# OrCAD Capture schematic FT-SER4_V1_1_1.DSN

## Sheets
1 INDEX: title: INDEX; rev: 1.1; note: 17 HaYetsira Street; note: Yokneam Illit, Israel 2069208
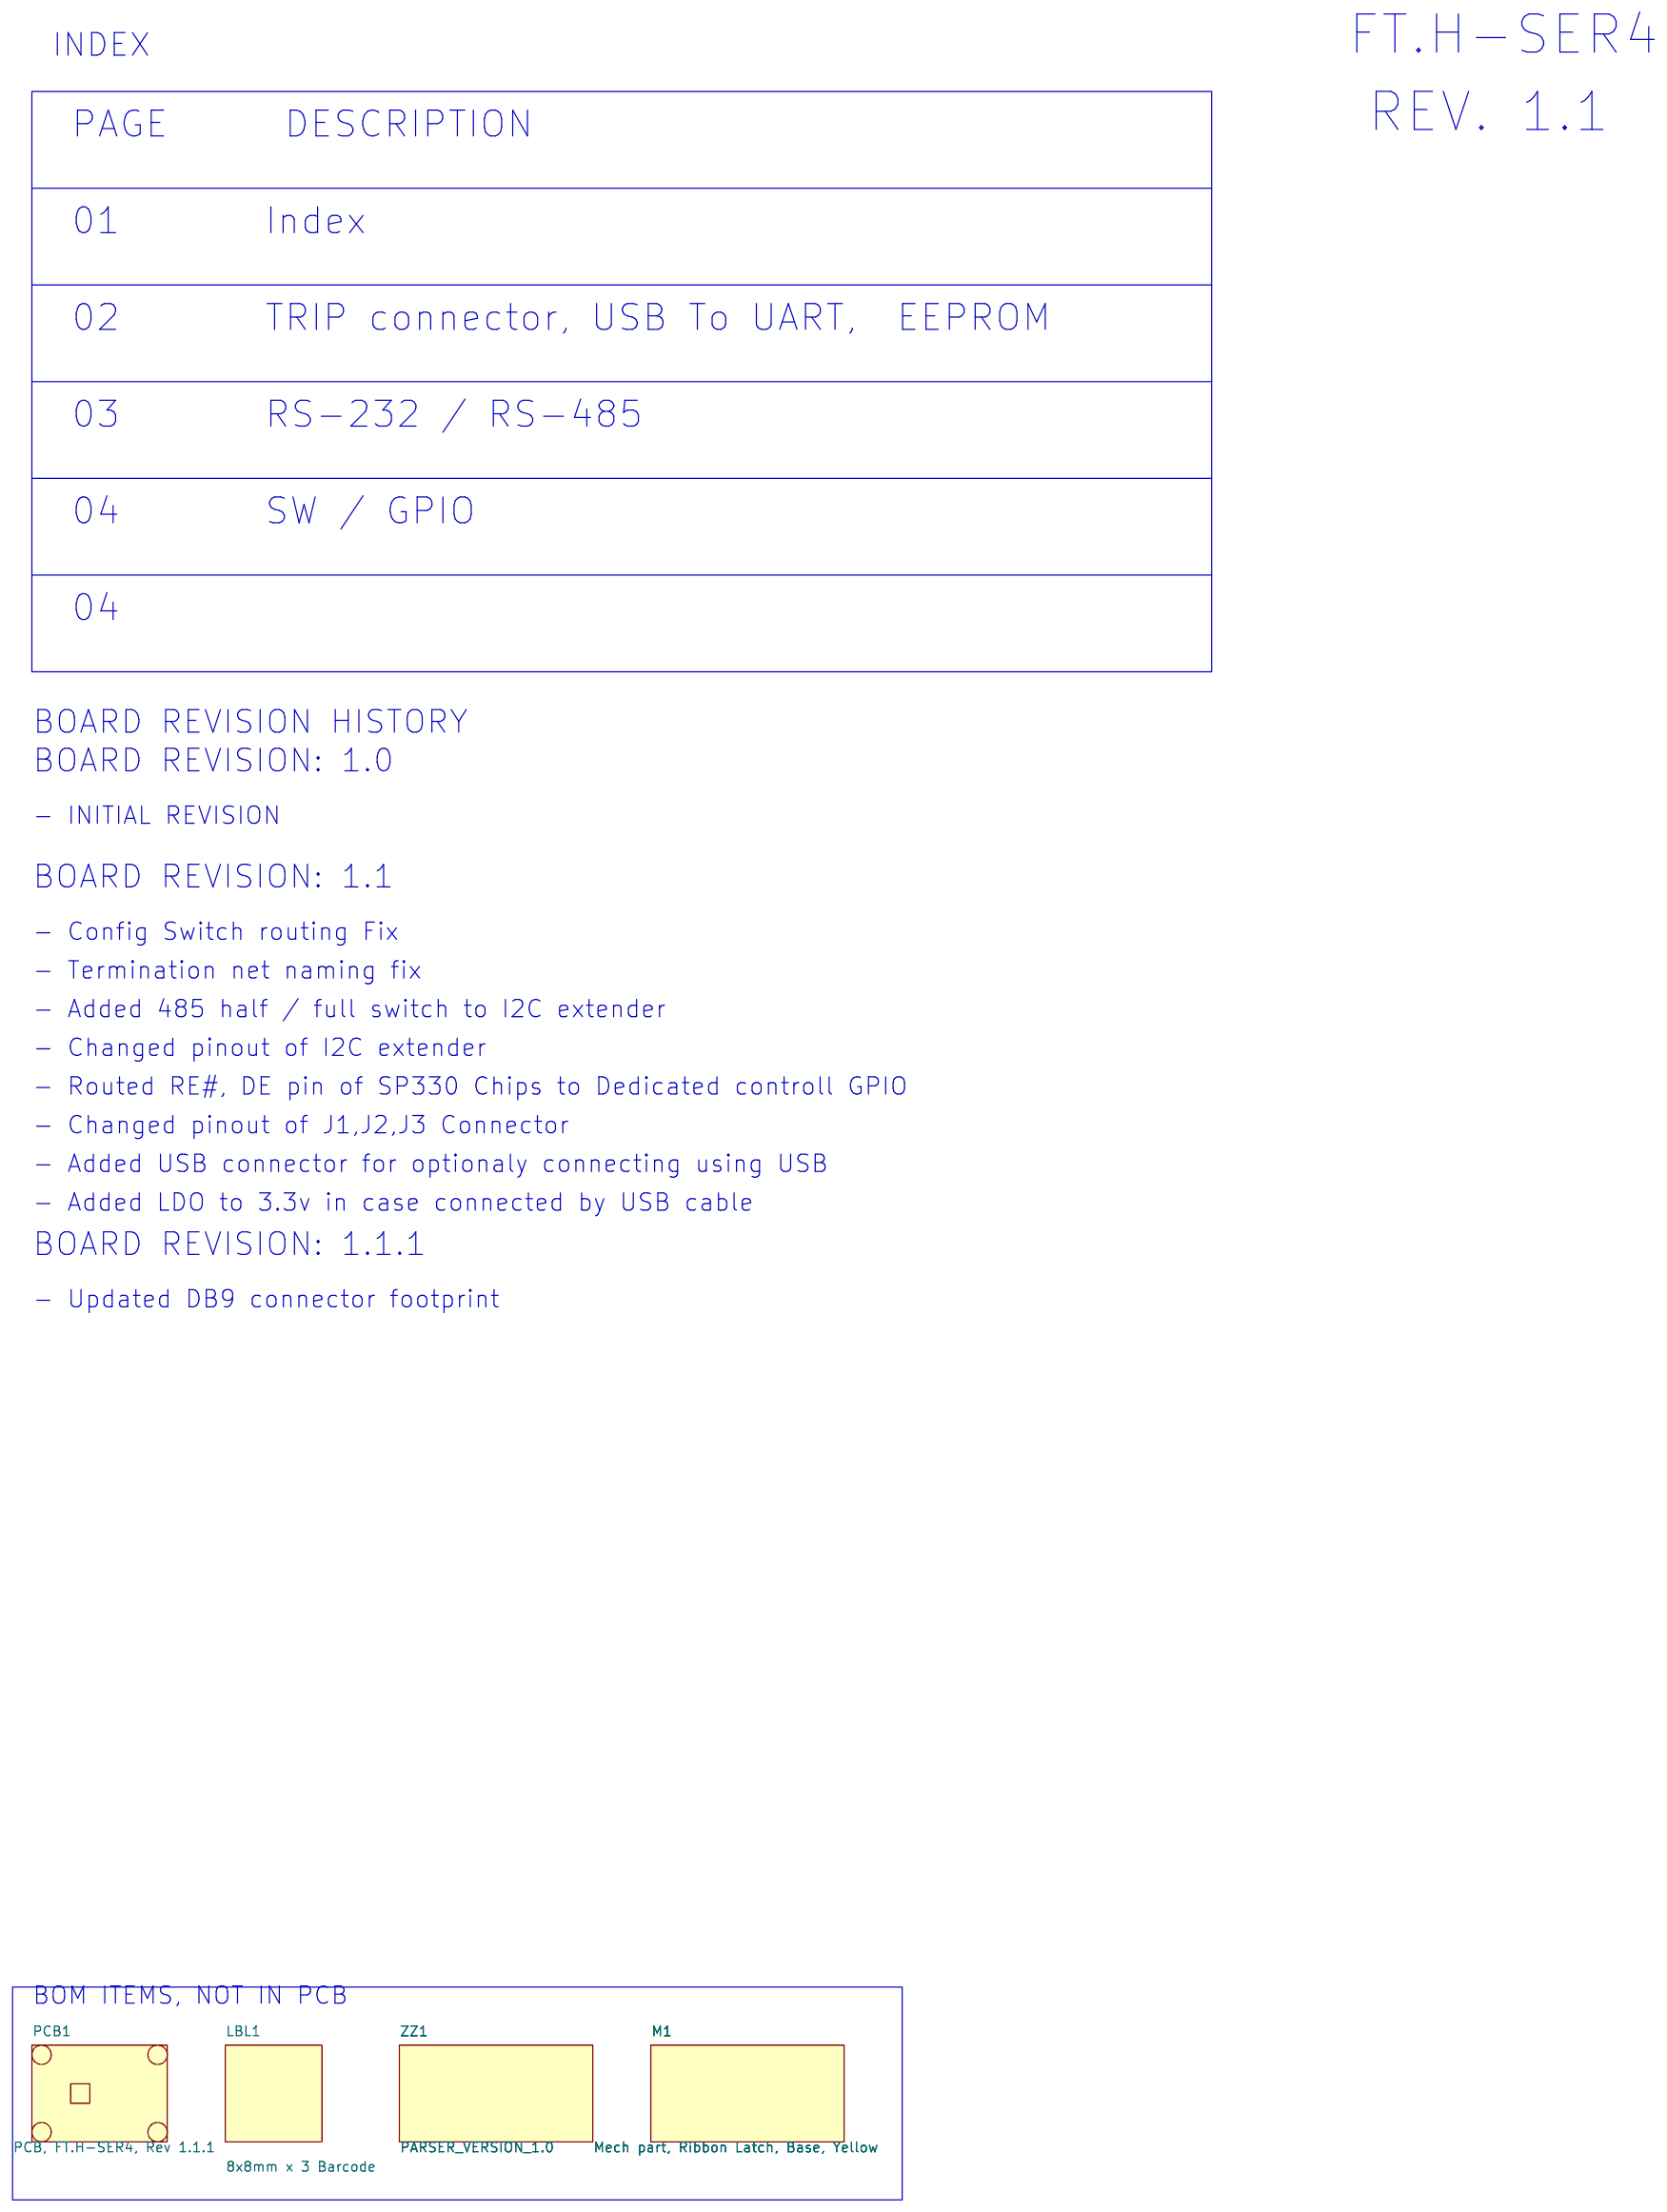
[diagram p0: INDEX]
2 TRIP + USB2UART: size A3; title: 02-TRIP + USB2UART
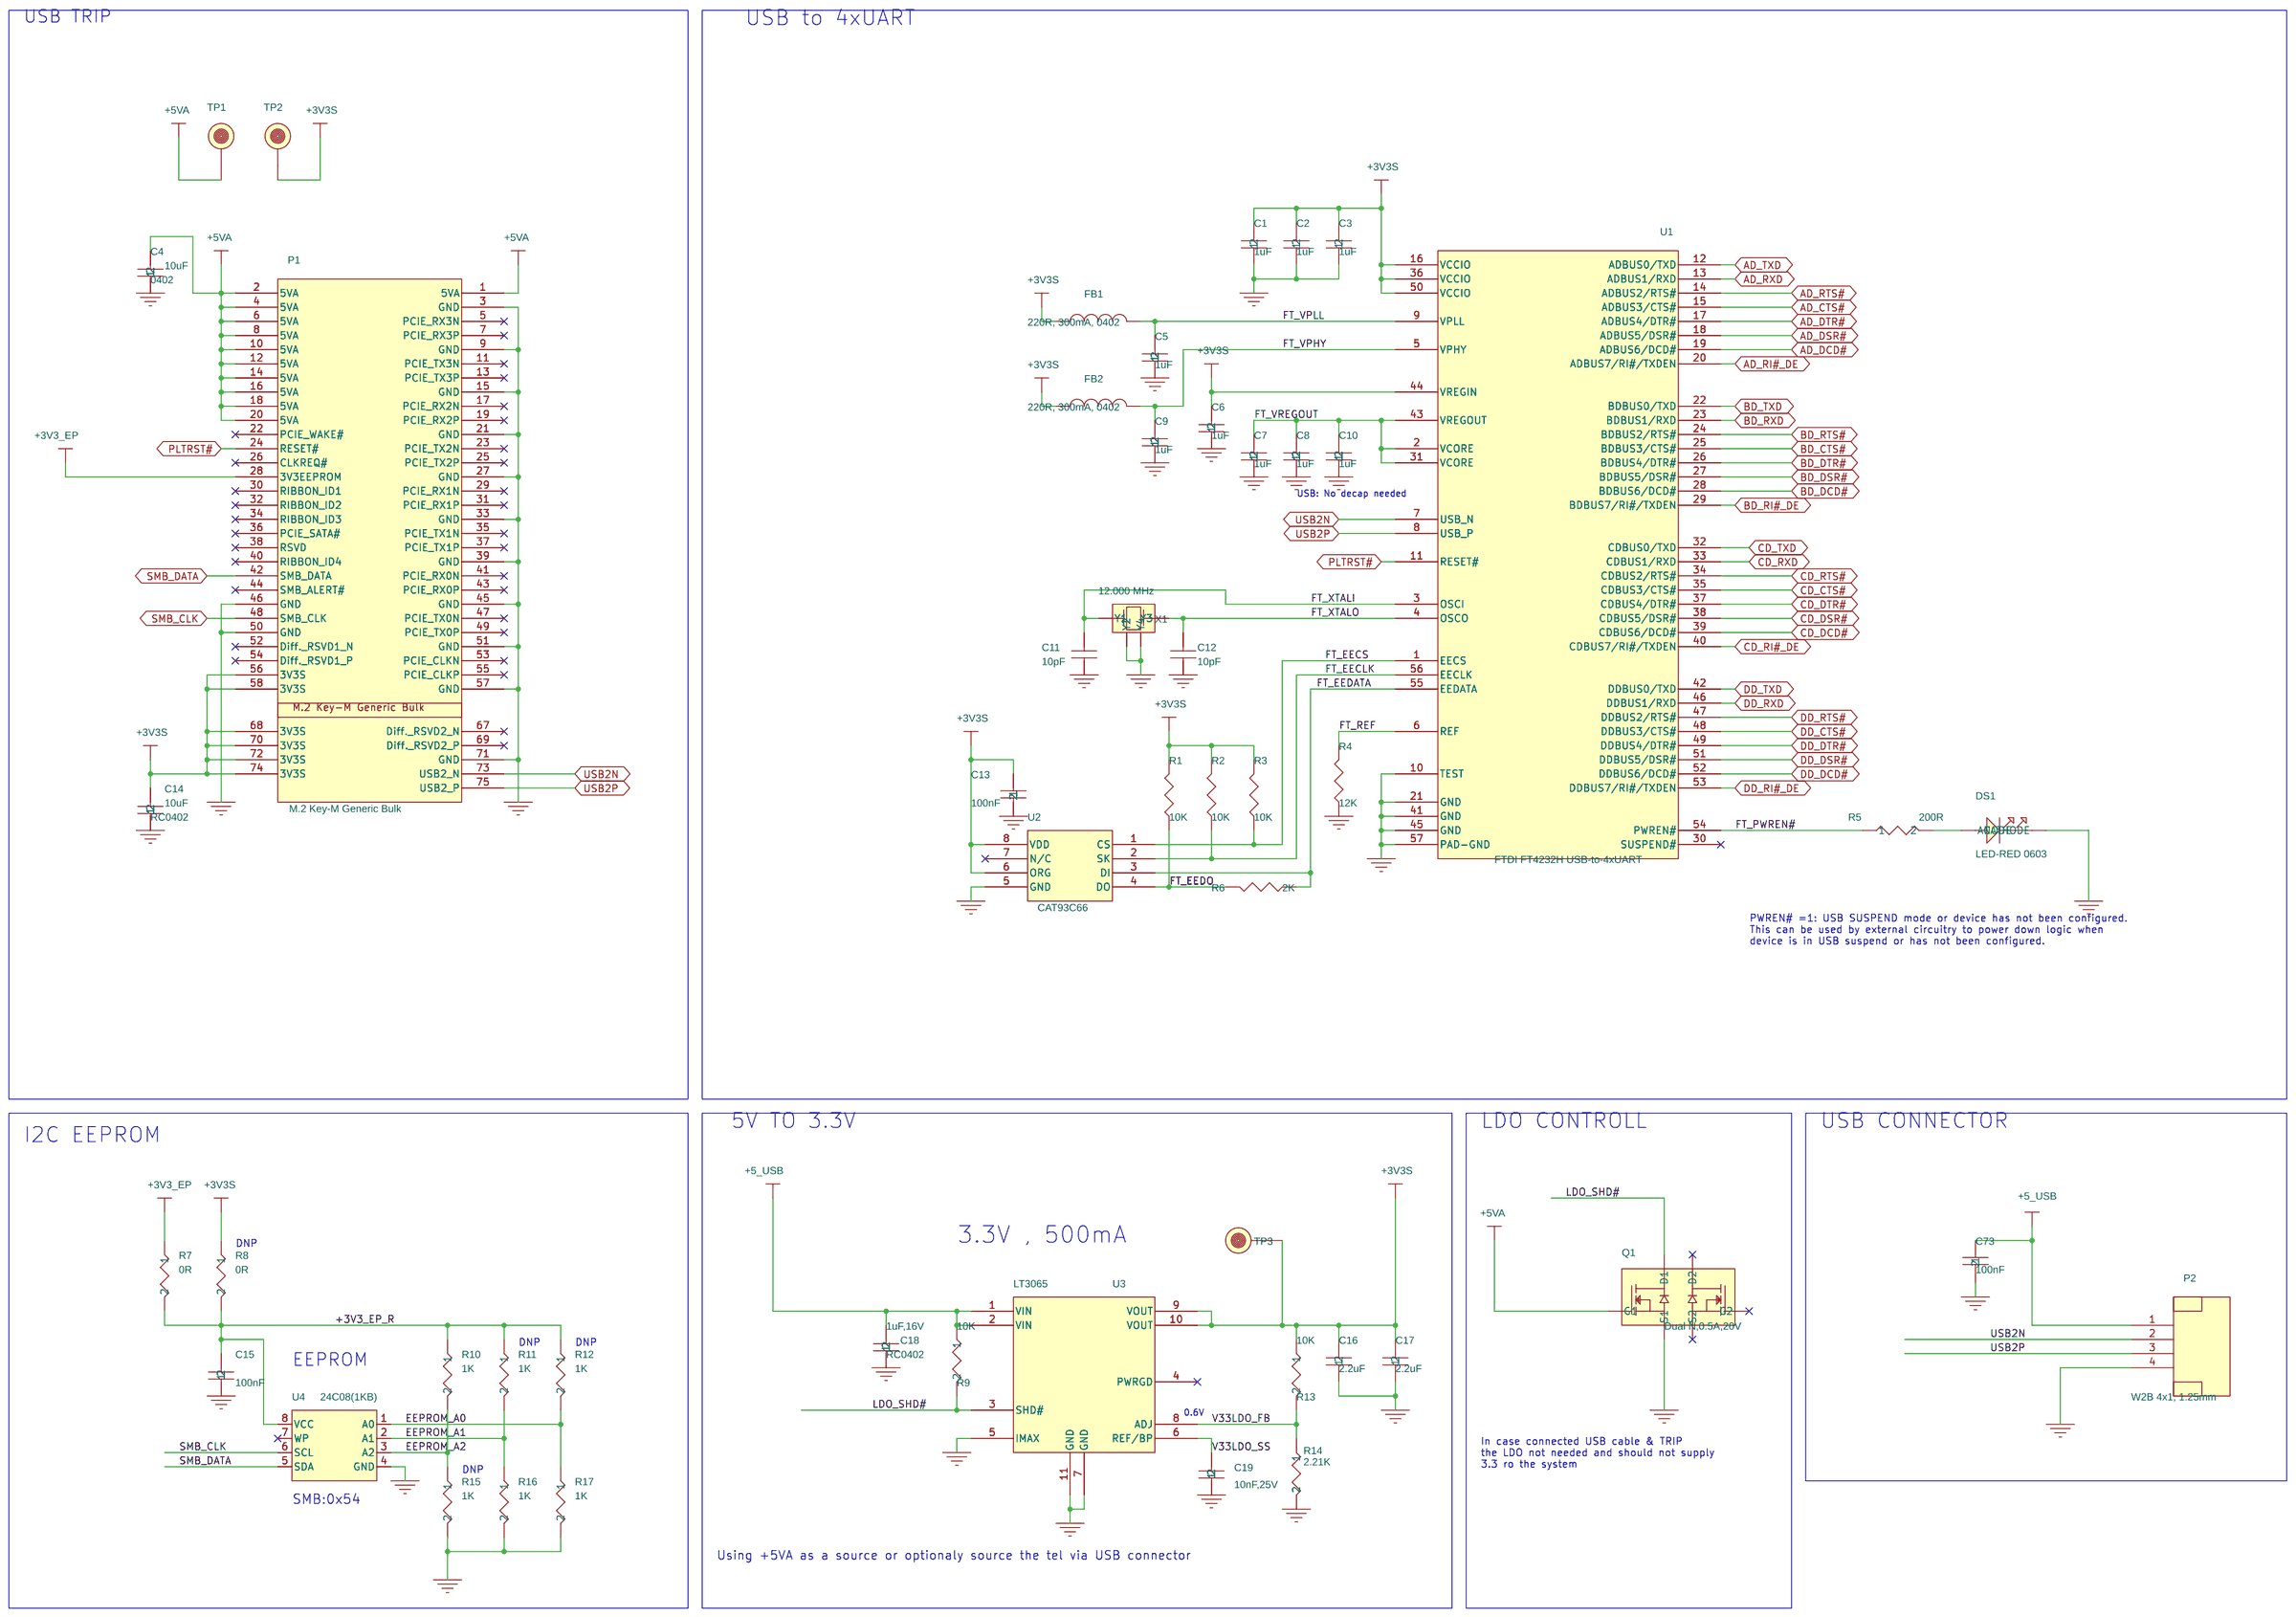
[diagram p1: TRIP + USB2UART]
3 RS232/RS485: size A3; title: 04-SW/GPIO
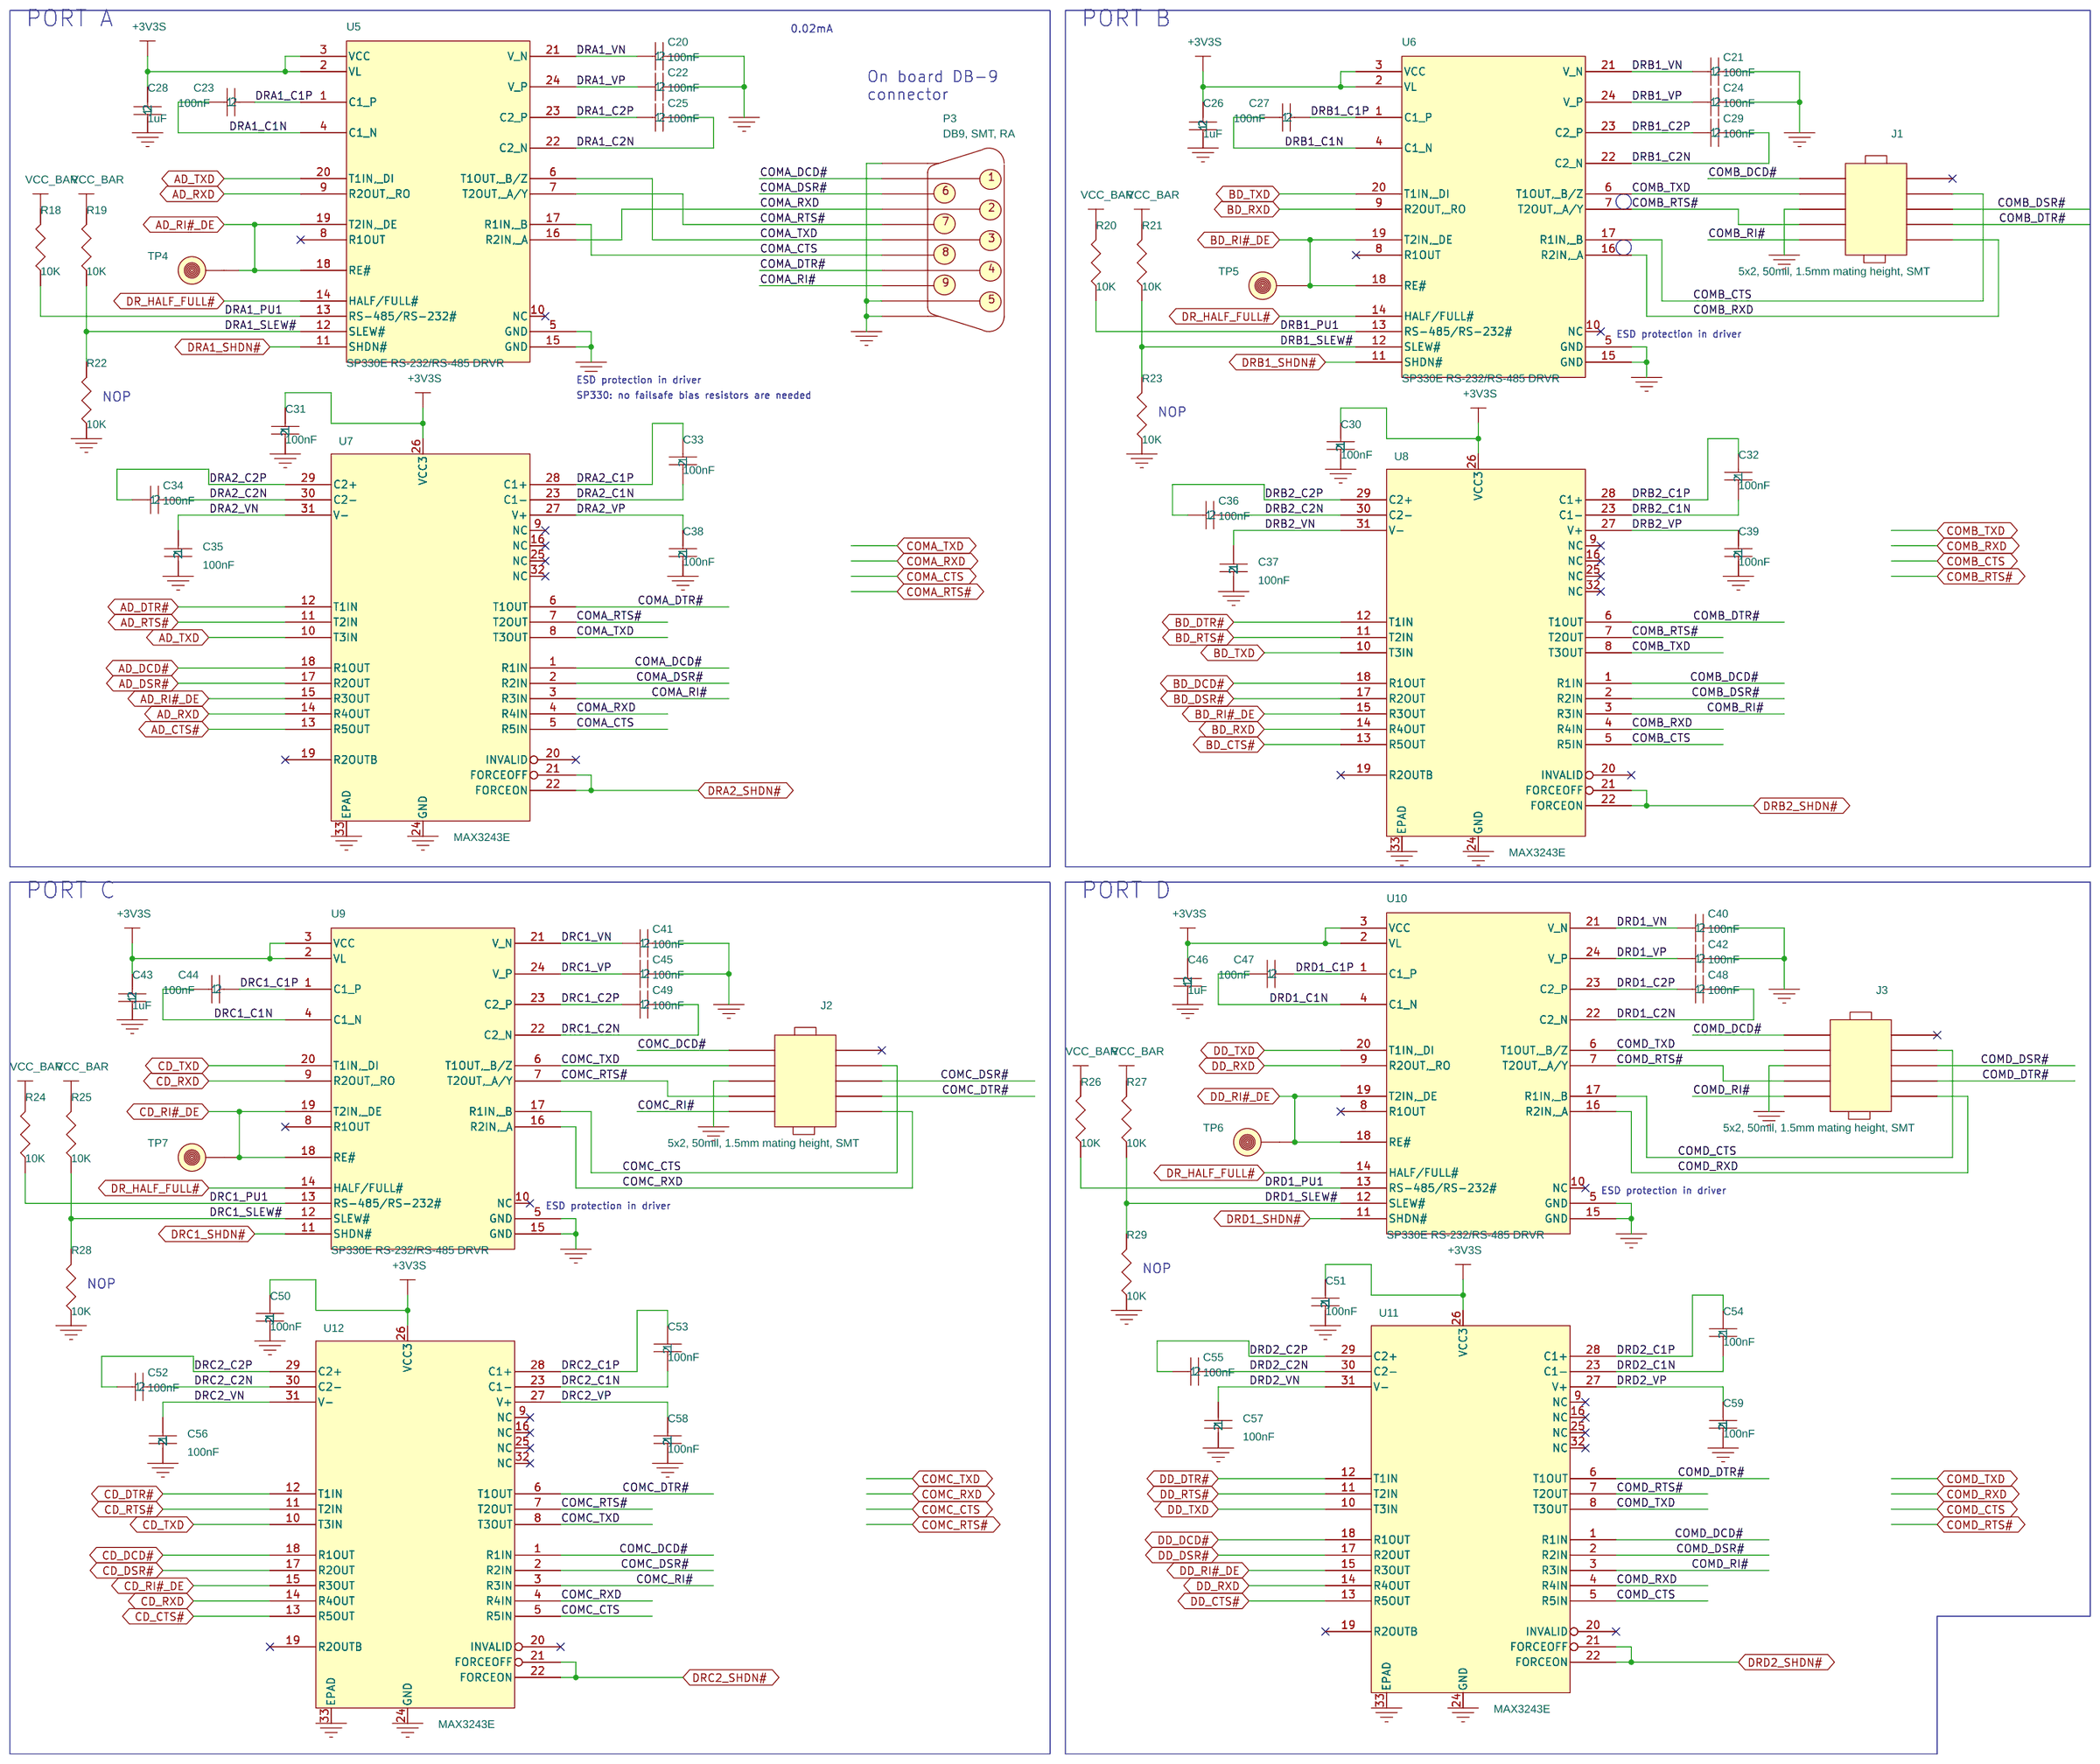
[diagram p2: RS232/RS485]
4 SW/GPIO: size A3; title: 03-RS232/RS485
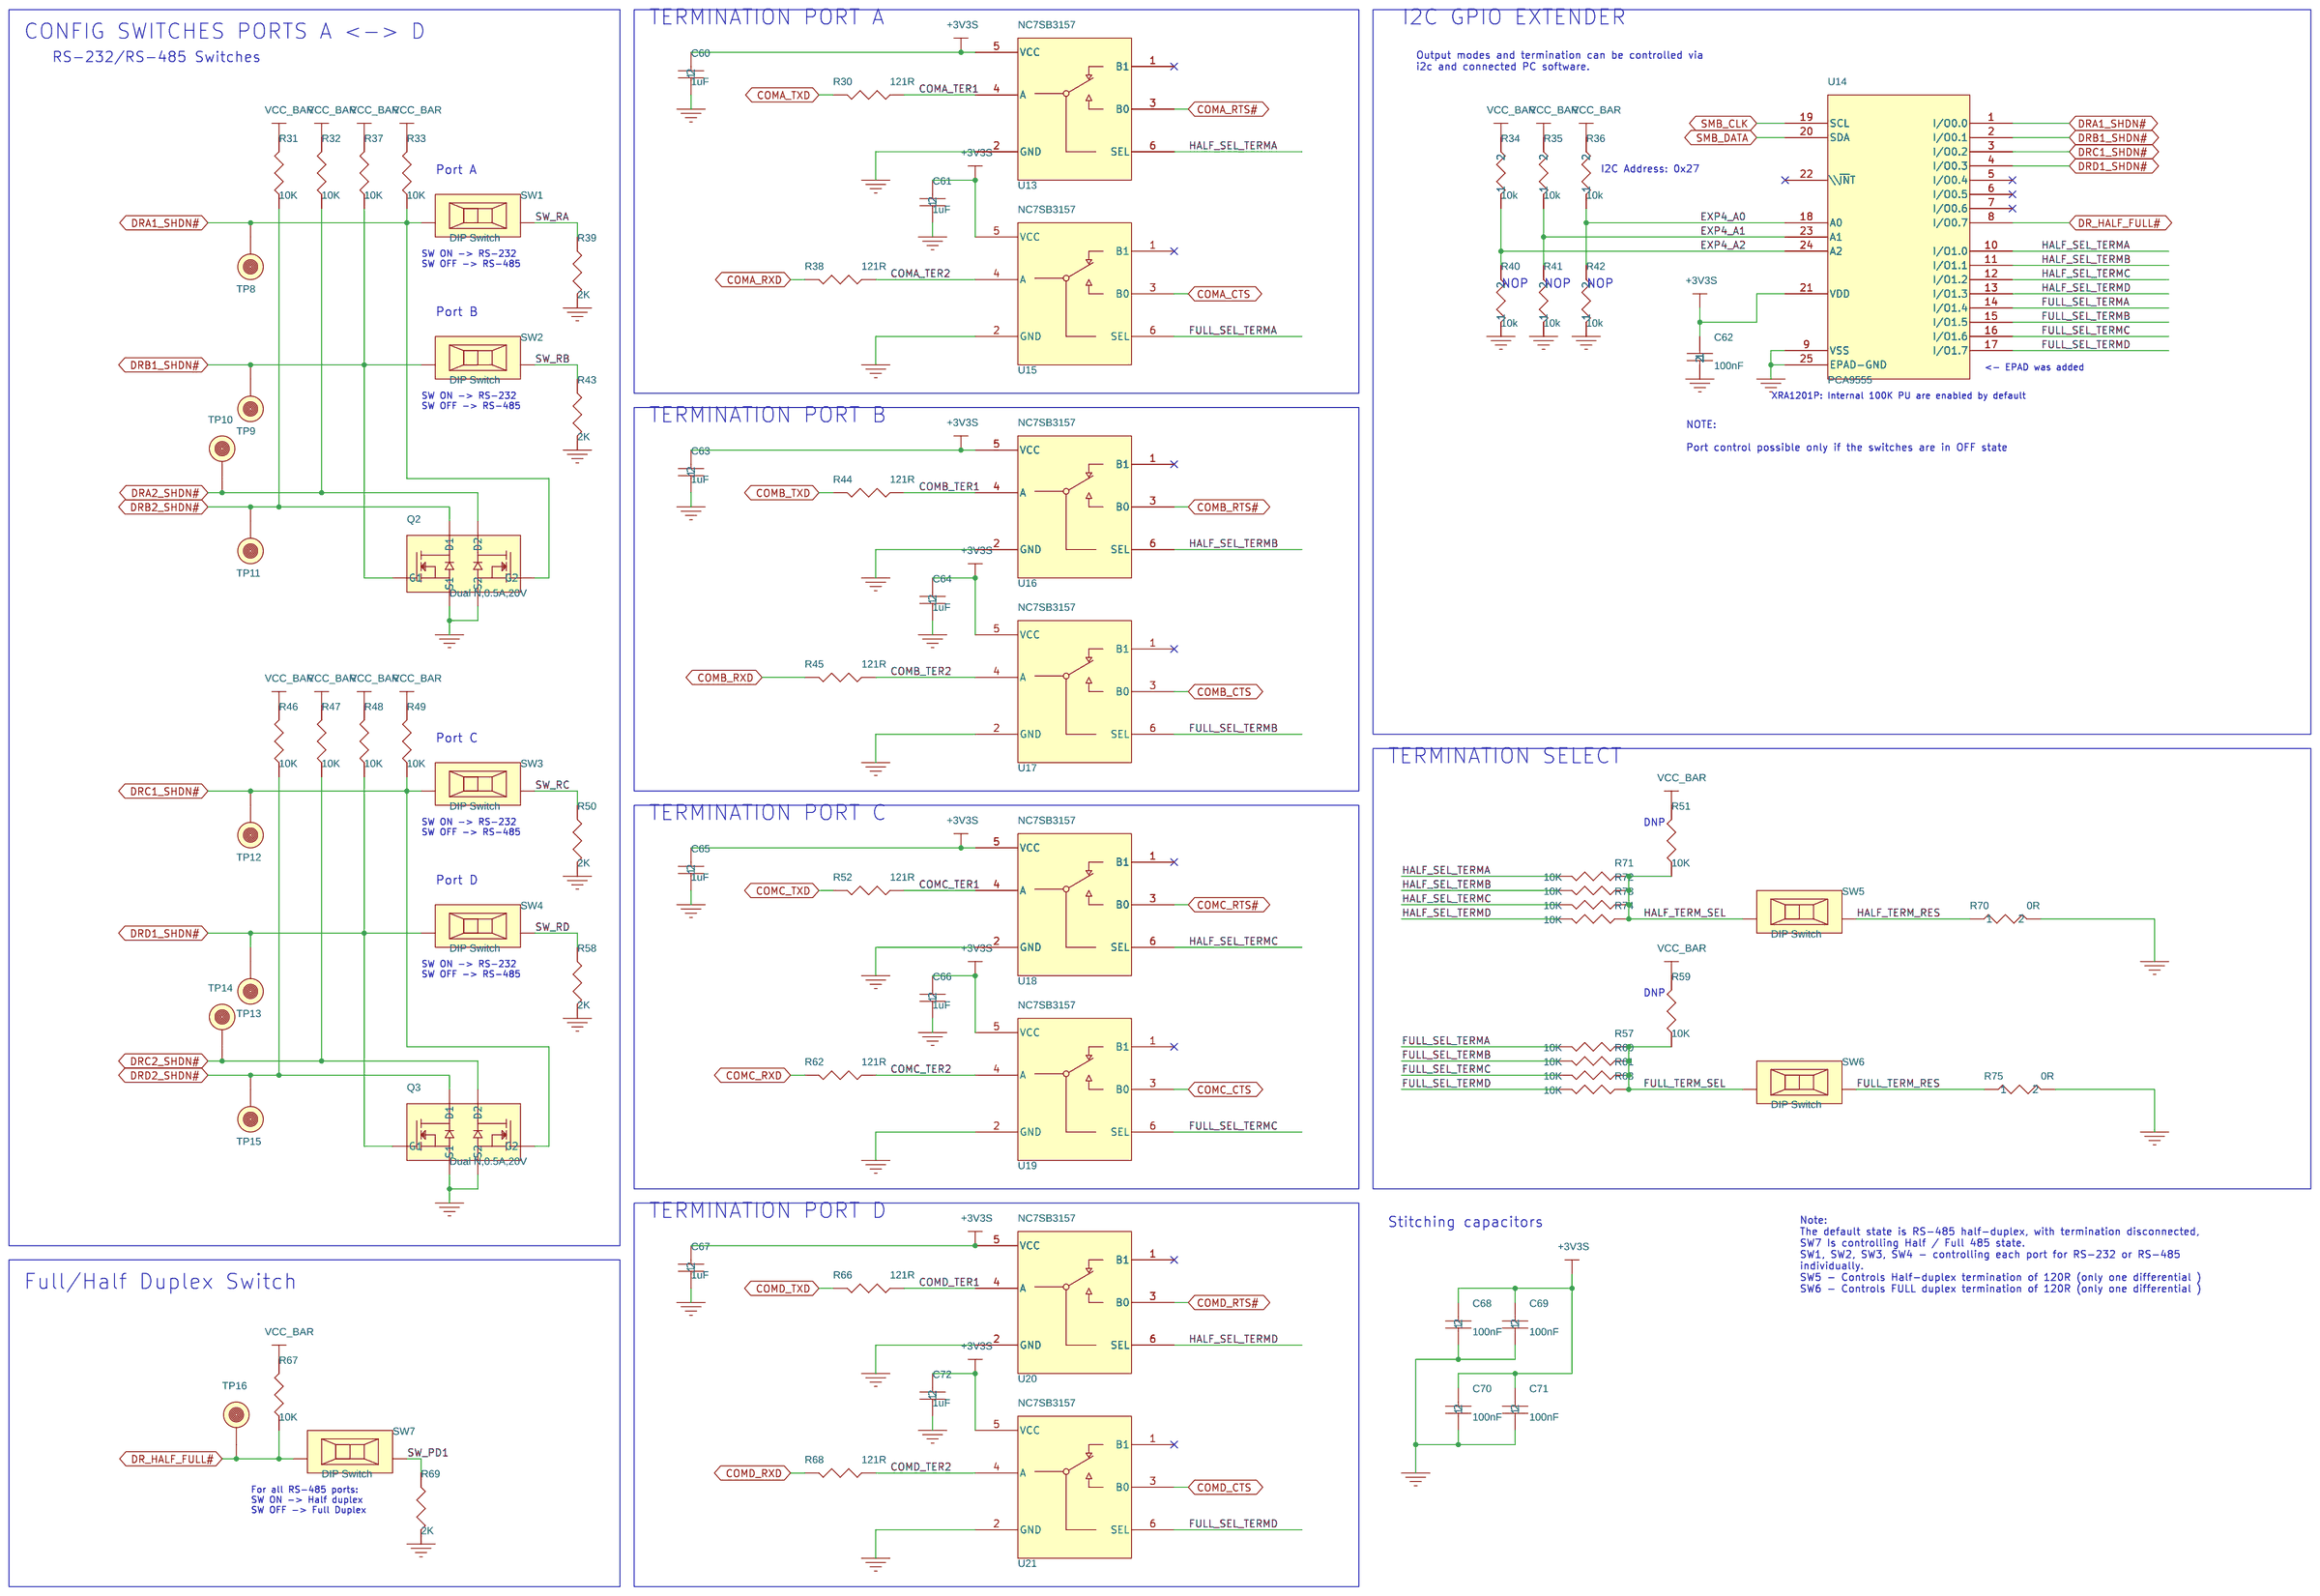
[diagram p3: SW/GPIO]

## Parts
sheet INDEX
LBL1  8x8mm x 3 Barcode  [LBL XYU]
M1  Mech part, Ribbon Latch, Base, Yellow
PCB1  PCB, FT.H-SER4, Rev 1.1.1
ZZ1  PARSER_VERSION_1.0
sheet RS232/RS485
C20  100nF  [RC0402]
C21  100nF  [RC0402]
C22  100nF  [RC0402]
C23  100nF  [RC0402]
C24  100nF  [RC0402]
C25  100nF  [RC0402]
C26  1uF  [RC0402]
C27  100nF  [RC0402]
C28  1uF  [RC0402]
C29  100nF  [RC0402]
C30  100nF  [RC0402]
C31  100nF  [RC0402]
C32  100nF  [RC0402]
C33  100nF  [RC0402]
C34  100nF  [RC0402]
C35  100nF  [RC0402]
C36  100nF  [RC0402]
C37  100nF  [RC0402]
C38  100nF  [RC0402]
C39  100nF  [RC0402]
C40  100nF  [RC0402]
C41  100nF  [RC0402]
C42  100nF  [RC0402]
C43  1uF  [RC0402]
C44  100nF  [RC0402]
C45  100nF  [RC0402]
C46  1uF  [RC0402]
C47  100nF  [RC0402]
C48  100nF  [RC0402]
C49  100nF  [RC0402]
C50  100nF  [RC0402]
C51  100nF  [RC0402]
C52  100nF  [RC0402]
C53  100nF  [RC0402]
C54  100nF  [RC0402]
C55  100nF  [RC0402]
C56  100nF  [RC0402]
C57  100nF  [RC0402]
C58  100nF  [RC0402]
C59  100nF  [RC0402]
J1  5x2, 50mil, 1.5mm mating height, SMT  [2X5SMHDR]
J2  5x2, 50mil, 1.5mm mating height, SMT  [2X5SMHDR]
J3  5x2, 50mil, 1.5mm mating height, SMT  [2X5SMHDR]
P3  DB9, SMT, RA
R18  10K  [RC0402]
R19  10K  [RC0402]
R20  10K  [RC0402]
R21  10K  [RC0402]
R22  10K  [RC0402]
R23  10K  [RC0402]
R24  10K  [RC0402]
R25  10K  [RC0402]
R26  10K  [RC0402]
R27  10K  [RC0402]
R28  10K  [RC0402]
R29  10K  [RC0402]
TP4  TP
TP5  TP
TP6  TP
TP7  TP
U5  SP330E RS-232/RS-485 DRVR
U6  SP330E RS-232/RS-485 DRVR
U7  MAX3243E  [QFN5x5-32]
U8  MAX3243E  [QFN5x5-32]
U9  SP330E RS-232/RS-485 DRVR
U10  SP330E RS-232/RS-485 DRVR
U11  MAX3243E  [QFN5x5-32]
U12  MAX3243E  [QFN5x5-32]
sheet SW/GPIO
C60  1uF  [RC0402]
C61  1uF  [RC0402]
C62  100nF  [RC0402]
C63  1uF  [RC0402]
C64  1uF  [RC0402]
C65  1uF  [RC0402]
C66  1uF  [RC0402]
C67  1uF  [RC0402]
C68  100nF  [RC0402]
C69  100nF  [RC0402]
C70  100nF  [RC0402]
C71  100nF  [RC0402]
C72  1uF  [RC0402]
Q2  Dual N,0.5A,20V  [SOT-563-6]
Q3  Dual N,0.5A,20V  [SOT-563-6]
R30  121R  [RC0402]
R31  10K  [RC0402]
R32  10K  [RC0402]
R33  10K  [RC0402]
R34  10k  [RC0402]
R35  10k  [RC0402]
R36  10k  [RC0402]
R37  10K  [RC0402]
R38  121R  [RC0402]
R39  2K  [RC0402]
R40  10k  [RC0402]
R41  10k  [RC0402]
R42  10k  [RC0402]
R43  2K  [RC0402]
R44  121R  [RC0402]
R45  121R  [RC0402]
R46  10K  [RC0402]
R47  10K  [RC0402]
R48  10K  [RC0402]
R49  10K  [RC0402]
R50  2K  [RC0402]
R51  10K  [RC0402]
R52  121R  [RC0402]
R57  10K  [RC0402]
R58  2K  [RC0402]
R59  10K  [RC0402]
R60  10K  [RC0402]
R61  10K  [RC0402]
R62  121R  [RC0402]
R63  10K  [RC0402]
R66  121R  [RC0402]
R67  10K  [RC0402]
R68  121R  [RC0402]
R69  2K  [RC0402]
R70  0R  [RC0402]
R71  10K  [RC0402]
R72  10K  [RC0402]
R73  10K  [RC0402]
R74  10K  [RC0402]
R75  0R  [RC0402]
SW1  DIP Switch  [SWDIP-1SM]
SW2  DIP Switch  [SWDIP-1SM]
SW3  DIP Switch  [SWDIP-1SM]
SW4  DIP Switch  [SWDIP-1SM]
SW5  DIP Switch  [SWDIP-1SM]
SW6  DIP Switch  [SWDIP-1SM]
SW7  DIP Switch  [SWDIP-1SM]
TP8  TP
TP9  TP
TP10  TP
TP11  TP
TP12  TP
TP13  TP
TP14  TP
TP15  TP
TP16  TP
U13  NC7SB3157  [SC70-6]
U14  PCA9555  [QFN4x4-24]
U15  NC7SB3157  [SC70-6]
U16  NC7SB3157  [SC70-6]
U17  NC7SB3157  [SC70-6]
U18  NC7SB3157  [SC70-6]
U19  NC7SB3157  [SC70-6]
U20  NC7SB3157  [SC70-6]
U21  NC7SB3157  [SC70-6]
sheet TRIP + USB2UART
C1  1uF  [RC0402]
C2  1uF  [RC0402]
C3  1uF  [RC0402]
C4  10uF  [0402]
C5  1uF  [RC0402]
C6  1uF  [RC0402]
C7  1uF  [RC0402]
C8  1uF  [RC0402]
C9  1uF  [RC0402]
C10  1uF  [RC0402]
C11  10pF  [RC0402]
C12  10pF  [RC0402]
C13  100nF  [RC0402]
C14  10uF  [RC0402]
C15  100nF  [RC0402]
C16  2.2uF  [RC0402]
C17  2.2uF  [RC0402]
C18  1uF,16V  [RC0402]
C19  10nF,25V  [RC0402]
C73  100nF  [RC0402]
DS1  LED-RED 0603  [LED-0603]
FB1  220R, 300mA, 0402  [FB0402]
FB2  220R, 300mA, 0402  [FB0402]
P1  M.2 Key-M Generic Bulk  [NGFF67P8HMkeySM]
P2  W2B 4x1, 1.25mm  [1x4W2B1_25RASM]
Q1  Dual N,0.5A,20V  [SOT-563-6]
R1  10K  [RC0402]
R2  10K  [RC0402]
R3  10K  [RC0402]
R4  12K  [RC0402]
R5  200R  [RC0402]
R6  2K  [RC0402]
R7  0R  [RC0402]
R8  0R  [RC0402]
R9  10K  [RC0402]
R10  1K  [RC0402]
R11  1K  [RC0402]
R12  1K  [RC0402]
R13  10K  [RC0402]
R14  2.21K  [RC0402]
R15  1K  [RC0402]
R16  1K  [RC0402]
R17  1K  [RC0402]
TP1  TP
TP2  TP
TP3  TP
U1  FTDI FT4232H USB-to-4xUART
U2  CAT93C66  [MO-229VCED-2]
U3  LT3065  [DFN3x3-10]
U4  24C08(1KB)  [MO-229VCED-2]
X1  12.000 MHz  [OSC3225]

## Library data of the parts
LBL1 = Label_8x8mm_x_3_for_Barcode: CLABCONF0: FT.H-SER4
M1 = PARSER_VERSION_1_0.0: CLABCONF0: FT.H-SER4; P/N: 290E010010
PCB1 = SBC-iHSW_Rev_1.0: CLABCONF0: FT.H-SER4; P/N: 188C03402
ZZ1 = PARSER_VERSION_1.0: CLABCONF0: FT.H-SER4
C20 = 15pF,_50V,_NPO,_5%,_0402_31: CLABCONF0: FT.H-SER4; P/N: 151B10400S
C21 = 15pF,_50V,_NPO,_5%,_0402_10: CLABCONF0: FT.H-SER4; P/N: 151B10400S
C22 = 15pF,_50V,_NPO,_5%,_0402_35: CLABCONF0: FT.H-SER4; P/N: 151B10400S
C23 = 15pF,_50V,_NPO,_5%,_0402_4: CLABCONF0: FT.H-SER4; P/N: 151B10400S
C24 C70 = 15pF,_50V,_NPO,_5%,_0402_12: CLABCONF0: FT.H-SER4; P/N: 151B10400S
C25 = 15pF,_50V,_NPO,_5%,_0402_26: CLABCONF0: FT.H-SER4; P/N: 151B10400S
C10 C26 C63 = 15pF,_50V,_NPO,_5%,_0402_3: CLABCONF0: FT.H-SER4; P/N: 151C10500S
C27 = 15pF,_50V,_NPO,_5%,_0402_24: CLABCONF0: FT.H-SER4; P/N: 151B10400S
C28 = 15pF,_50V,_NPO,_5%,_0402_22: CLABCONF0: FT.H-SER4; P/N: 151C10500S
C29 = 15pF,_50V,_NPO,_5%,_0402_39: CLABCONF0: FT.H-SER4; P/N: 151B10400S
C30 = 15pF,_50V,_NPO,_5%,_0402_14: CLABCONF0: FT.H-SER4; P/N: 151B10400S
C31 = 15pF,_50V,_NPO,_5%,_0402_28: CLABCONF0: FT.H-SER4; P/N: 151B10400S
C32 = 15pF,_50V,_NPO,_5%,_0402_21: CLABCONF0: FT.H-SER4; P/N: 151B10400S
C33 = 15pF,_50V,_NPO,_5%,_0402: CLABCONF0: FT.H-SER4; P/N: 151B10400S
C34 = 15pF,_50V,_NPO,_5%,_0402_37: CLABCONF0: FT.H-SER4; P/N: 151B10400S
C35 C69 = 15pF,_50V,_NPO,_5%,_0402_9: CLABCONF0: FT.H-SER4; P/N: 151B10400S
C36 = 15pF,_50V,_NPO,_5%,_0402_17: CLABCONF0: FT.H-SER4; P/N: 151B10400S
C37 = 15pF,_50V,_NPO,_5%,_0402_29: CLABCONF0: FT.H-SER4; P/N: 151B10400S
C38 = 15pF,_50V,_NPO,_5%,_0402_6: CLABCONF0: FT.H-SER4; P/N: 151B10400S
C39 = 15pF,_50V,_NPO,_5%,_0402_25: CLABCONF0: FT.H-SER4; P/N: 151B10400S
C40 = 15pF,_50V,_NPO,_5%,_0402_5: CLABCONF0: FT.H-SER4; P/N: 151B10400S
C41 = 15pF,_50V,_NPO,_5%,_0402_30: CLABCONF0: FT.H-SER4; P/N: 151B10400S
C42 C62 = 15pF,_50V,_NPO,_5%,_0402_11: CLABCONF0: FT.H-SER4; P/N: 151B10400S
C43 = 15pF,_50V,_NPO,_5%,_0402_20: CLABCONF0: FT.H-SER4; P/N: 151C10500S
C44 = 15pF,_50V,_NPO,_5%,_0402_2: CLABCONF0: FT.H-SER4; P/N: 151B10400S
C45 = 15pF,_50V,_NPO,_5%,_0402_32: CLABCONF0: FT.H-SER4; P/N: 151B10400S
C46 = 15pF,_50V,_NPO,_5%,_0402_34: CLABCONF0: FT.H-SER4; P/N: 151C10500S
C47 = 15pF,_50V,_NPO,_5%,_0402_16: CLABCONF0: FT.H-SER4; P/N: 151B10400S
C48 = 15pF,_50V,_NPO,_5%,_0402_36: CLABCONF0: FT.H-SER4; P/N: 151B10400S
C49 = 15pF,_50V,_NPO,_5%,_0402_18: CLABCONF0: FT.H-SER4; P/N: 151B10400S
C50 = 15pF,_50V,_NPO,_5%,_0402_27: CLABCONF0: FT.H-SER4; P/N: 151B10400S
C13 C51 C68 = 15pF,_50V,_NPO,_5%,_0402_8: CLABCONF0: FT.H-SER4; P/N: 151B10400S
C52 = 15pF,_50V,_NPO,_5%,_0402_33: CLABCONF0: FT.H-SER4; P/N: 151B10400S
C53 = 15pF,_50V,_NPO,_5%,_0402_38: CLABCONF0: FT.H-SER4; P/N: 151B10400S
C54 = 15pF,_50V,_NPO,_5%,_0402_15: CLABCONF0: FT.H-SER4; P/N: 151B10400S
C55 = 15pF,_50V,_NPO,_5%,_0402_13: CLABCONF0: FT.H-SER4; P/N: 151B10400S
C56 = 15pF,_50V,_NPO,_5%,_0402_7: CLABCONF0: FT.H-SER4; P/N: 151B10400S
C57 = 15pF,_50V,_NPO,_5%,_0402_23: CLABCONF0: FT.H-SER4; P/N: 151B10400S
C15 C58 C71 = 15pF,_50V,_NPO,_5%,_0402_1: CLABCONF0: FT.H-SER4; P/N: 151B10400S
C59 = 15pF,_50V,_NPO,_5%,_0402_19: CLABCONF0: FT.H-SER4; P/N: 151B10400S
J1-J3 = HEADER_5x2_M_1: CLABCONF0: FT.H-SER4; P/N: 190C01002S
P3 = DB9,_SMT,_RA: CLABCONF0: FT.H-SER4; P/N: 180C00901S
R1-R3 R18-R21 R24-R27 R31-R33 R37 R46-R49 R57 R60 R61 R63 R67 R71-R74 = 10K,1%,0402,1_16W_0: CLABCONF0: FT.H-SER4; Group: Always
R22 R23 R28 R29 R51 R59 = 10K,1%,0402,1_16W_0: CLABCONF0: =DNP; Group: Always
TP1-TP16 = TP_SMT: CLABCONF0: =DNP
U5 U6 U9 U10 = SP330E_RS-232_RS-485_DRVR: CLABCONF0: FT.H-SER4; P/N: 116A00330S
U7 U8 U11 U12 = MAX3243E_RS-232_3T5R_BGA: CLABCONF0: FT.H-SER4
C1 C60 = 15pF,_50V,_NPO,_5%,_0402_10: CLABCONF0: FT.H-SER4; P/N: 151C10500S
C6 C61 = 15pF,_50V,_NPO,_5%,_0402_6: CLABCONF0: FT.H-SER4; P/N: 151C10500S
C5 C64 = 15pF,_50V,_NPO,_5%,_0402: CLABCONF0: FT.H-SER4; P/N: 151C10500S
C3 C65 = 15pF,_50V,_NPO,_5%,_0402_7: CLABCONF0: FT.H-SER4; P/N: 151C10500S
C8 C66 = 15pF,_50V,_NPO,_5%,_0402_4: CLABCONF0: FT.H-SER4; P/N: 151C10500S
C2 C67 = 15pF,_50V,_NPO,_5%,_0402_5: CLABCONF0: FT.H-SER4; P/N: 151C10500S
C9 C72 = 15pF,_50V,_NPO,_5%,_0402_2: CLABCONF0: FT.H-SER4; P/N: 151C10500S
Q1-Q3 = DUAL_N-MOSFET,_0.5A_20V: CLABCONF0: FT.H-SER4
R30 R38 R44 R45 R52 R62 R66 R68 = 10K,1%,0402,1_16W_0: CLABCONF0: FT.H-SER4; Group: Always; P/N: 161C12101S
R34 = 1M_,5%,_0402_5: CLABCONF0: FT.H-SER4; P/N: 161C10021S
R35 = 1M_,5%,_0402_2: CLABCONF0: FT.H-SER4; P/N: 161C10021S
R36 = 1M_,5%,_0402: CLABCONF0: FT.H-SER4; P/N: 161C10021S
R6 R39 R43 R50 R58 R69 = 10K,1%,0402,1_16W_0: CLABCONF0: FT.H-SER4; Group: Always; P/N: 161C20011S
R40 = 1M_,5%,_0402_3: CLABCONF0: =DNP; P/N: 161C10021S
R41 = 1M_,5%,_0402_4: CLABCONF0: =DNP; P/N: 161C10021S
R42 = 1M_,5%,_0402_1: CLABCONF0: =DNP; P/N: 161C10021S
R70 = 348R,1%,0402,1_16W_1: CLABCONF0: FT.H-SER4; P/N: 161C00005S
R75 = 348R,1%,0402,1_16W: CLABCONF0: FT.H-SER4; P/N: 161C00005S
SW1-SW7 = SW_DIP_Switch_x1: CLABCONF0: FT.H-SER4; P/N: 170I30100S
U13 U15-U21 = Bus_switch_2_1: CLABCONF0: FT.H-SER4
U14 = PCA9555_0: CLABCONF0: FT.H-SER4
C4 = 100nF,_10V,_X7R,_10%,_0402_4: CLABCONF0: FT.H-SER4; P/N: 151B10600S
C7 = 15pF,_50V,_NPO,_5%,_0402_9: CLABCONF0: FT.H-SER4; P/N: 151C10500S
C11 C12 = 10pF,50V,NPO,_5%,_0402_0: CLABCONF0: FT.H-SER4
C14 = 100nF,_10V,_X7R,_10%,_0402_3: CLABCONF0: FT.H-SER4; P/N: 151B10600S
C16 = 100nF,_10V,_X7R,_10%,_0402: CLABCONF0: FT.H-SER4; P/N: 151A22500S
C17 = 100nF,_10V,_X7R,_10%,_0402_6: CLABCONF0: FT.H-SER4; P/N: 151A22500S
C18 = 100nF,_10V,_X7R,_10%,_0402_2: CLABCONF0: FT.H-SER4; P/N: 151C10500S
C19 = 100nF,_10V,_X7R,_10%,_0402_5: CLABCONF0: FT.H-SER4; P/N: 151A22500S
C73 = 100nF,_10V,_X7R,_10%,_0402_1: CLABCONF0: FT.H-SER4
DS1 = LED-RED_0603: CLABCONF0: FT.H-SER4
FB1 = Ferrite_bead_,_120_Ohm@3A_1: CLABCONF0: FT.H-SER4; P/N: 147D22100S
FB2 = Ferrite_bead_,_120_Ohm@3A: CLABCONF0: FT.H-SER4; P/N: 147D22100S
P1 = M.2_Key-M_Generic_Bulk: CLABCONF0: FT.H-SER4; P/N: 182K06700S
P2 = W2B_4x1_HDR,_1.25mm: CLABCONF0: FT.H-SER4; P/N: 182E00401S
R4 = 10K,1%,0402,1_16W_0: CLABCONF0: FT.H-SER4; Group: Always; P/N: 161C12021S
R5 = 0R_1: CLABCONF0: FT.H-SER4; P/N: 161C20001S
R7 = 348R,1%,0402,1_16W_7: CLABCONF0: FT.H-SER4; P/N: 161C00005S
R8 = 348R,1%,0402,1_16W_3: CLABCONF0: =DNP; P/N: 161C00005S
R9 = 0R: CLABCONF0: FT.H-SER4; P/N: 161C10021S
R10 = 348R,1%,0402,1_16W_1: CLABCONF0: FT.H-SER4; P/N: 161C10011S
R11 = 348R,1%,0402,1_16W_5: CLABCONF0: =DNP; P/N: 161C10011S
R12 = 348R,1%,0402,1_16W_4: CLABCONF0: =DNP; P/N: 161C10011S
R13 = 0R_3: CLABCONF0: FT.H-SER4; P/N: 161C10021S
R14 = 0R_2: CLABCONF0: FT.H-SER4; P/N: 161C22111S
R15 = 348R,1%,0402,1_16W_2: CLABCONF0: =DNP; P/N: 161C10011S
R16 = 348R,1%,0402,1_16W: CLABCONF0: FT.H-SER4; P/N: 161C10011S
R17 = 348R,1%,0402,1_16W_6: CLABCONF0: FT.H-SER4; P/N: 161C10011S
U1 = FTDI_FT4232H_USB-to-4xUART_0: CLABCONF0: FT.H-SER4; P/N: 116A00350S
U2 = 93C66: CLABCONF0: FT.H-SER4; P/N: 111S40800S
U3 = LT3065_0: CLABCONF0: FT.H-SER4; P/N: 123M0R601S
U4 = 24C02,_serial_EE,_2KB,_I2C: CLABCONF0: FT.H-SER4; P/N: 111S31000S
X1 = XTAL_25Mhz: CLABCONF0: FT.H-SER4

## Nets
+3V3_EP: P1.28(3V3EEPROM) R7.1
+3V3_EP_R: C15.2 R7.2 R8.2 R10.1 R11.1 R12.1 U4.8(VCC)
+3V3S: C1.2 C2.2 C3.2 C6.2 C13.1 C14.2 C16.2 C17.2 C26.2 C28.2 C30.1 C31.1 C43.2 C46.2 C50.1 C51.1 C60.2 C61.2 C62.1 C63.2 C64.2 C65.2 C66.2 C67.2 C68.2 C69.2 C70.2 C71.2 C72.2 FB1.1 FB2.1 P1.56(3V3S) P1.58(3V3S) P1.68(3V3S) P1.70(3V3S) P1.72(3V3S) P1.74(3V3S) R1.2 R2.2 R3.2 R8.1 R13.1 R18.2 R19.2 R20.2 R21.2 R24.2 R25.2 R26.2 R27.2 R31.2 R32.2 R33.2 R34.2 R35.2 R36.2 R37.2 R46.2 R47.2 R48.2 R49.2 R51.2 R59.2 R67.2 TP2.1 TP3.1 U1.16(VCCIO) U1.36(VCCIO) U1.44(VREGIN) U1.50(VCCIO) U2.6(ORG) U2.8(VDD) U3.9(VOUT) U3.10(VOUT) U5.2(VL) U5.3(VCC) U6.2(VL) U6.3(VCC) U7.26(VCC3) U8.26(VCC3) U9.2(VL) U9.3(VCC) U10.2(VL) U10.3(VCC) U11.26(VCC3) U12.26(VCC3) U13.5(VCC) U14.21(VDD) U15.5(VCC) U16.5(VCC) U17.5(VCC) U18.5(VCC) U19.5(VCC) U20.5(VCC) U21.5(VCC)
+5VA: C4.2 P1.1(5VA) P1.2(5VA) P1.4(5VA) P1.6(5VA) P1.8(5VA) P1.10(5VA) P1.12(5VA) P1.14(5VA) P1.16(5VA) P1.18(5VA) P1.20(5VA) Q1.2(G1) TP1.1
GND: C1.1 C2.1 C3.1 C4.1 C5.1 C6.1 C7.1 C8.1 C9.1 C10.1 C11.1 C12.1 C13.2 C14.1 C15.1 C16.1 C17.1 C18.1 C19.1 C20.2 C21.2 C22.2 C24.2 C26.1 C28.1 C30.2 C31.2 C35.2 C37.2 C38.2 C39.2 C40.2 C41.2 C42.2 C43.1 C45.2 C46.1 C50.2 C51.2 C56.2 C57.2 C58.2 C59.2 C60.1 C61.1 C62.2 C63.1 C64.1 C65.1 C66.1 C67.1 C68.1 C69.1 C70.1 C71.1 C72.1 C73.2 DS1.CATHODE J1.3 J2.3 J3.3 P1.3(GND) P1.9(GND) P1.15(GND) P1.21(GND) P1.27(GND) P1.33(GND) P1.39(GND) P1.45(GND) P1.46(GND) P1.50(GND) P1.51(GND) P1.57(GND) P1.71(GND) P2.4 P3.5 P3.10 P3.11 Q1.1(S1) Q2.1(S1) Q2.4(S2) Q3.1(S1) Q3.4(S2) R4.1 R14.2 R15.2 R16.2 R17.2 R22.1 R23.1 R28.1 R29.1 R39.2 R40.1 R41.1 R42.1 R43.2 R50.2 R58.2 R69.2 R70.2 R75.2 U1.10(TEST) U1.21(GND) U1.41(GND) U1.45(GND) U1.57(PAD-GND) U2.5(GND) U3.5(IMAX) U3.7(GND) U3.11(GND) U4.4(GND) U5.5(GND) U5.15(GND) U6.5(GND) U6.15(GND) U7.24(GND) U7.33(EPAD) U8.24(GND) U8.33(EPAD) U9.5(GND) U9.15(GND) U10.5(GND) U10.15(GND) U11.24(GND) U11.33(EPAD) U12.24(GND) U12.33(EPAD) U13.2(GND) U14.9(VSS) U14.25(EPAD-GND) U15.2(GND) U16.2(GND) U17.2(GND) U18.2(GND) U19.2(GND) U20.2(GND) U21.2(GND) X1.2(Y2) X1.4(Y4)
V33LDO_FB: R13.2 R14.1 U3.8(ADJ)
V33LDO_SS: C19.2 U3.6(REF/BP)
+5_USB: C18.2 C73.1 P2.1 R9.1 U3.1(VIN) U3.2(VIN)
AD_CTS#: U1.15(ADBUS3/CTS#) U7.13(R5OUT)
AD_DCD#: U1.19(ADBUS6/DCD#) U7.18(R1OUT)
AD_DSR#: U1.18(ADBUS5/DSR#) U7.17(R2OUT)
AD_DTR#: U1.17(ADBUS4/DTR#) U7.12(T1IN)
AD_RI#_DE: TP4.1 U1.20(ADBUS7/RI#/TXDEN) U5.18(RE#) U5.19(T2IN,_DE) U7.15(R3OUT)
AD_RTS#: U1.14(ADBUS2/RTS#) U7.11(T2IN)
AD_RXD: U1.13(ADBUS1/RXD) U5.9(R2OUT,_RO) U7.14(R4OUT)
AD_TXD: U1.12(ADBUS0/TXD) U5.20(T1IN,_DI) U7.10(T3IN)
BD_CTS#: U1.25(BDBUS3/CTS#) U8.13(R5OUT)
BD_DCD#: U1.28(BDBUS6/DCD#) U8.18(R1OUT)
BD_DSR#: U1.27(BDBUS5/DSR#) U8.17(R2OUT)
BD_DTR#: U1.26(BDBUS4/DTR#) U8.12(T1IN)
BD_RI#_DE: TP5.1 U1.29(BDBUS7/RI#/TXDEN) U6.18(RE#) U6.19(T2IN,_DE) U8.15(R3OUT)
BD_RTS#: U1.24(BDBUS2/RTS#) U8.11(T2IN)
BD_RXD: U1.23(BDBUS1/RXD) U6.9(R2OUT,_RO) U8.14(R4OUT)
BD_TXD: U1.22(BDBUS0/TXD) U6.20(T1IN,_DI) U8.10(T3IN)
CD_CTS#: U1.35(CDBUS3/CTS#) U12.13(R5OUT)
CD_DCD#: U1.39(CDBUS6/DCD#) U12.18(R1OUT)
CD_DSR#: U1.38(CDBUS5/DSR#) U12.17(R2OUT)
CD_DTR#: U1.37(CDBUS4/DTR#) U12.12(T1IN)
CD_RI#_DE: TP7.1 U1.40(CDBUS7/RI#/TXDEN) U9.18(RE#) U9.19(T2IN,_DE) U12.15(R3OUT)
CD_RTS#: U1.34(CDBUS2/RTS#) U12.11(T2IN)
CD_RXD: U1.33(CDBUS1/RXD) U9.9(R2OUT,_RO) U12.14(R4OUT)
CD_TXD: U1.32(CDBUS0/TXD) U9.20(T1IN,_DI) U12.10(T3IN)
COMA_CTS: P3.8 U5.17(R1IN,_B) U7.5(R5IN) U15.3(B0)
COMA_DCD#: P3.1 U7.1(R1IN)
COMA_DSR#: P3.6 U7.2(R2IN)
COMA_DTR#: P3.4 U7.6(T1OUT)
COMA_RI#: P3.9 U7.3(R3IN)
COMA_RTS#: P3.7 U5.7(T2OUT,_A/Y) U7.7(T2OUT) U13.3(B0)
COMA_RXD: P3.2 R38.2 U5.16(R2IN,_A) U7.4(R4IN)
COMA_TER1: R30.1 U13.4(A)
COMA_TER2: R38.1 U15.4(A)
COMA_TXD: P3.3 R30.2 U5.6(T1OUT,_B/Z) U7.8(T3OUT)
COMB_CTS: J1.7 U6.17(R1IN,_B) U8.5(R5IN) U17.3(B0)
COMB_DCD#: J1.1 U8.1(R1IN)
COMB_DSR#: J1.8 U8.2(R2IN)
COMB_DTR#: J1.9 U8.6(T1OUT)
COMB_RI#: J1.5 U8.3(R3IN)
COMB_RTS#: J1.4 U6.7(T2OUT,_A/Y) U8.7(T2OUT) U16.3(B0)
COMB_RXD: J1.10 R45.2 U6.16(R2IN,_A) U8.4(R4IN)
COMB_TER1: R44.1 U16.4(A)
COMB_TER2: R45.1 U17.4(A)
COMB_TXD: J1.2 R44.2 U6.6(T1OUT,_B/Z) U8.8(T3OUT)
COMC_CTS: J2.7 U9.17(R1IN,_B) U12.5(R5IN) U19.3(B0)
COMC_DCD#: J2.1 U12.1(R1IN)
COMC_DSR#: J2.8 U12.2(R2IN)
COMC_DTR#: J2.9 U12.6(T1OUT)
COMC_RI#: J2.5 U12.3(R3IN)
COMC_RTS#: J2.4 U9.7(T2OUT,_A/Y) U12.7(T2OUT) U18.3(B0)
COMC_RXD: J2.10 R62.2 U9.16(R2IN,_A) U12.4(R4IN)
COMC_TER1: R52.1 U18.4(A)
COMC_TER2: R62.1 U19.4(A)
COMC_TXD: J2.2 R52.2 U9.6(T1OUT,_B/Z) U12.8(T3OUT)
COMD_CTS: J3.7 U10.17(R1IN,_B) U11.5(R5IN) U21.3(B0)
COMD_DCD#: J3.1 U11.1(R1IN)
COMD_DSR#: J3.8 U11.2(R2IN)
COMD_DTR#: J3.9 U11.6(T1OUT)
COMD_RI#: J3.5 U11.3(R3IN)
COMD_RTS#: J3.4 U10.7(T2OUT,_A/Y) U11.7(T2OUT) U20.3(B0)
COMD_RXD: J3.10 R68.2 U10.16(R2IN,_A) U11.4(R4IN)
COMD_TER1: R66.1 U20.4(A)
COMD_TER2: R68.1 U21.4(A)
COMD_TXD: J3.2 R66.2 U10.6(T1OUT,_B/Z) U11.8(T3OUT)
DD_CTS#: U1.48(DDBUS3/CTS#) U11.13(R5OUT)
DD_DCD#: U1.52(DDBUS6/DCD#) U11.18(R1OUT)
DD_DSR#: U1.51(DDBUS5/DSR#) U11.17(R2OUT)
DD_DTR#: U1.49(DDBUS4/DTR#) U11.12(T1IN)
DD_RI#_DE: TP6.1 U1.53(DDBUS7/RI#/TXDEN) U10.18(RE#) U10.19(T2IN,_DE) U11.15(R3OUT)
DD_RTS#: U1.47(DDBUS2/RTS#) U11.11(T2IN)
DD_RXD: U1.46(DDBUS1/RXD) U10.9(R2OUT,_RO) U11.14(R4OUT)
DD_TXD: U1.42(DDBUS0/TXD) U10.20(T1IN,_DI) U11.10(T3IN)
DR_HALF_FULL#: R67.1 SW7.1 TP16.1 U5.14(HALF/FULL#) U6.14(HALF/FULL#) U9.14(HALF/FULL#) U10.14(HALF/FULL#) U14.8(I/O0.7)
DRA1_C1N: C23.1 U5.4(C1_N)
DRA1_C1P: C23.2 U5.1(C1_P)
DRA1_C2N: C25.2 U5.22(C2_N)
DRA1_C2P: C25.1 U5.23(C2_P)
DRA1_PU1: R18.1 U5.13(RS-485/RS-232#)
DRA1_SHDN#: Q2.5(G2) R33.1 SW1.1 TP8.1 U5.11(SHDN#) U14.1(I/O0.0)
DRA1_SLEW#: R19.1 R22.2 U5.12(SLEW#)
DRA1_VN: C20.1 U5.21(V_N)
DRA1_VP: C22.1 U5.24(V_P)
DRA2_C1N: C33.2 U7.23(C1-)
DRA2_C1P: C33.1 U7.28(C1+)
DRA2_C2N: C34.2 U7.30(C2-)
DRA2_C2P: C34.1 U7.29(C2+)
DRA2_SHDN#: Q2.3(D2) R32.1 TP10.1 U7.21(FORCEOFF) U7.22(FORCEON)
DRA2_VN: C35.1 U7.31(V-)
DRA2_VP: C38.1 U7.27(V+)
DRB1_C1N: C27.1 U6.4(C1_N)
DRB1_C1P: C27.2 U6.1(C1_P)
DRB1_C2N: C29.2 U6.22(C2_N)
DRB1_C2P: C29.1 U6.23(C2_P)
DRB1_PU1: R20.1 U6.13(RS-485/RS-232#)
DRB1_SHDN#: Q2.2(G1) R37.1 SW2.1 TP9.1 U6.11(SHDN#) U14.2(I/O0.1)
DRB1_SLEW#: R21.1 R23.2 U6.12(SLEW#)
DRB1_VN: C21.1 U6.21(V_N)
DRB1_VP: C24.1 U6.24(V_P)
DRB2_C1N: C32.2 U8.23(C1-)
DRB2_C1P: C32.1 U8.28(C1+)
DRB2_C2N: C36.2 U8.30(C2-)
DRB2_C2P: C36.1 U8.29(C2+)
DRB2_SHDN#: Q2.6(D1) R31.1 TP11.1 U8.21(FORCEOFF) U8.22(FORCEON)
DRB2_VN: C37.1 U8.31(V-)
DRB2_VP: C39.1 U8.27(V+)
DRC1_C1N: C44.1 U9.4(C1_N)
DRC1_C1P: C44.2 U9.1(C1_P)
DRC1_C2N: C49.2 U9.22(C2_N)
DRC1_C2P: C49.1 U9.23(C2_P)
DRC1_PU1: R24.1 U9.13(RS-485/RS-232#)
DRC1_SHDN#: Q3.5(G2) R49.1 SW3.1 TP12.1 U9.11(SHDN#) U14.3(I/O0.2)
DRC1_SLEW#: R25.1 R28.2 U9.12(SLEW#)
DRC1_VN: C41.1 U9.21(V_N)
DRC1_VP: C45.1 U9.24(V_P)
DRC2_C1N: C53.2 U12.23(C1-)
DRC2_C1P: C53.1 U12.28(C1+)
DRC2_C2N: C52.2 U12.30(C2-)
DRC2_C2P: C52.1 U12.29(C2+)
DRC2_SHDN#: Q3.3(D2) R47.1 TP14.1 U12.21(FORCEOFF) U12.22(FORCEON)
DRC2_VN: C56.1 U12.31(V-)
DRC2_VP: C58.1 U12.27(V+)
DRD1_C1N: C47.1 U10.4(C1_N)
DRD1_C1P: C47.2 U10.1(C1_P)
DRD1_C2N: C48.2 U10.22(C2_N)
DRD1_C2P: C48.1 U10.23(C2_P)
DRD1_PU1: R26.1 U10.13(RS-485/RS-232#)
DRD1_SHDN#: Q3.2(G1) R48.1 SW4.1 TP13.1 U10.11(SHDN#) U14.4(I/O0.3)
DRD1_SLEW#: R27.1 R29.2 U10.12(SLEW#)
DRD1_VN: C40.1 U10.21(V_N)
DRD1_VP: C42.1 U10.24(V_P)
DRD2_C1N: C54.2 U11.23(C1-)
DRD2_C1P: C54.1 U11.28(C1+)
DRD2_C2N: C55.2 U11.30(C2-)
DRD2_C2P: C55.1 U11.29(C2+)
DRD2_SHDN#: Q3.6(D1) R46.1 TP15.1 U11.21(FORCEOFF) U11.22(FORCEON)
DRD2_VN: C57.1 U11.31(V-)
DRD2_VP: C59.1 U11.27(V+)
EEPROM_A0: R12.2 R17.1 U4.1(A0)
EEPROM_A1: R11.2 R16.1 U4.2(A1)
EEPROM_A2: R10.2 R15.1 U4.3(A2)
EXP4_A0: R36.1 R42.2 U14.18(A0)
EXP4_A1: R35.1 R41.2 U14.23(A1)
EXP4_A2: R34.1 R40.2 U14.24(A2)
FT_EECLK: R2.1 U1.56(EECLK) U2.2(SK)
FT_EECS: R3.1 U1.1(EECS) U2.1(CS)
FT_EEDATA: R6.1 U1.55(EEDATA) U2.3(DI)
FT_EEDO: R1.1 R6.2 U2.4(DO)
FT_PWREN#: R5.1 U1.54(PWREN#)
FT_REF: R4.2 U1.6(REF)
FT_VPHY: C9.2 FB2.2 U1.5(VPHY)
FT_VPLL: C5.2 FB1.2 U1.9(VPLL)
FT_VREGOUT: C7.2 C8.2 C10.2 U1.2(VCORE) U1.31(VCORE) U1.43(VREGOUT)
FT_XTALI: C11.2 U1.3(OSCI) X1.1(Y1)
FT_XTALO: C12.2 U1.4(OSCO) X1.3(Y3)
FULL_SEL_TERMA: R57.2 U14.14(I/O1.4) U15.6(SEL)
FULL_SEL_TERMB: R60.2 U14.15(I/O1.5) U17.6(SEL)
FULL_SEL_TERMC: R61.2 U14.16(I/O1.6) U19.6(SEL)
FULL_SEL_TERMD: R63.2 U14.17(I/O1.7) U21.6(SEL)
FULL_TERM_RES: R75.1 SW6.2
FULL_TERM_SEL: R57.1 R59.1 R60.1 R61.1 R63.1 SW6.1
HALF_SEL_TERMA: R71.2 U13.6(SEL) U14.10(I/O1.0)
HALF_SEL_TERMB: R72.2 U14.11(I/O1.1) U16.6(SEL)
HALF_SEL_TERMC: R73.2 U14.12(I/O1.2) U18.6(SEL)
HALF_SEL_TERMD: R74.2 U14.13(I/O1.3) U20.6(SEL)
HALF_TERM_RES: R70.1 SW5.2
HALF_TERM_SEL: R51.1 R71.1 R72.1 R73.1 R74.1 SW5.1
LDO_SHD#: Q1.6(D1) R9.2 U3.3(SHD#)
PLTRST#: P1.24(RESET#) U1.11(RESET#)
SMB_CLK: P1.48(SMB_CLK) U4.6(SCL) U14.19(SCL)
SMB_DATA: P1.42(SMB_DATA) U4.5(SDA) U14.20(SDA)
SW_PD1: R69.1 SW7.2
SW_RA: R39.1 SW1.2
SW_RB: R43.1 SW2.2
SW_RC: R50.1 SW3.2
SW_RD: R58.1 SW4.2
USB2N: P1.73(USB2_N) P2.2 U1.7(USB_N)
USB2P: P1.75(USB2_P) P2.3 U1.8(USB_P)
N16838203: DS1.ANODE R5.2

Not connected (* = marked no-connect by the designer): J1 6*; J2 6*; J3 6*; P1 5(PCIE_RX3N)* 7(PCIE_RX3P)* 11(PCIE_TX3N)* 13(PCIE_TX3P)* 17(PCIE_RX2N)* 19(PCIE_RX2P)* 22(PCIE_WAKE#)* 23(PCIE_TX2N)* 25(PCIE_TX2P)* 26(CLKREQ#)* 29(PCIE_RX1N)* 30(RIBBON_ID1)* 31(PCIE_RX1P)* 32(RIBBON_ID2)* 34(RIBBON_ID3)* 35(PCIE_TX1N)* 36(PCIE_SATA#)* 37(PCIE_TX1P)* 38(RSVD)* 40(RIBBON_ID4)* 41(PCIE_RX0N)* 43(PCIE_RX0P)* 44(SMB_ALERT#)* 47(PCIE_TX0N)* 49(PCIE_TX0P)* 52(Diff._RSVD1_N)* 53(PCIE_CLKN)* 54(Diff._RSVD1_P)* 55(PCIE_CLKP)* 67(Diff._RSVD2_N)* 69(Diff._RSVD2_P)*; Q1 3(D2)* 4(S2)* 5(G2)*; U1 30(SUSPEND#)*; U2 7(N/C)*; U3 4(PWRGD)*; U4 7(WP)*; U5 8(R1OUT)* 10(NC)*; U6 8(R1OUT)* 10(NC)*; U7 9(NC)* 16(NC)* 19(R2OUTB)* 20(INVALID)* 25(NC)* 32(NC)*; U8 9(NC)* 16(NC)* 19(R2OUTB)* 20(INVALID)* 25(NC)* 32(NC)*; U9 8(R1OUT)* 10(NC)*; U10 8(R1OUT)* 10(NC)*; U11 9(NC)* 16(NC)* 19(R2OUTB)* 20(INVALID)* 25(NC)* 32(NC)*; U12 9(NC)* 16(NC)* 19(R2OUTB)* 20(INVALID)* 25(NC)* 32(NC)*; U13 1(B1)*; U14 5(I/O0.4)* 6(I/O0.5)* 7(I/O0.6)* 22(\\~{IN}T)*; U15 1(B1)*; U16 1(B1)*; U17 1(B1)*; U18 1(B1)*; U19 1(B1)*; U20 1(B1)*; U21 1(B1)*

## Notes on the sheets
sheet 1
- FT.H-SER4
- INDEX
- REV. 1.1
- PAGE
- DESCRIPTION
- 01
- Index
- 02
- TRIP connector, USB To UART,  EEPROM
- 03
- RS-232 / RS-485
- 04
- SW / GPIO
- 04
- BOARD REVISION HISTORY
- BOARD REVISION: 1.0
- - INITIAL REVISION
- BOARD REVISION: 1.1
- - Config Switch routing Fix
- - Termination net naming fix
- - Added 485 half / full switch to I2C extender
- - Changed pinout of I2C extender
- - Routed RE#, DE pin of SP330 Chips to Dedicated controll GPIO
- - Changed pinout of J1,J2,J3 Connector
- - Added USB connector for optionaly connecting using USB
- - Added LDO to 3.3v in case connected by USB cable
- BOARD REVISION: 1.1.1
- - Updated DB9 connector footprint
- BOM ITEMS, NOT IN PCB
sheet 2
- USB TRIP
- USB to 4xUART
- USB: No decap needed
- PWREN# =1: USB SUSPEND mode or device has not been configured.
  This can be used by external circuitry to power down logic when
  device is in USB suspend or has not been configured.
- 5V TO 3.3V
- LDO CONTROLL
- USB CONNECTOR
- I2C EEPROM
- 3.3V , 500mA
- DNP
- DNP
- DNP
- EEPROM
- 0.6V
- In case connected USB cable & TRIP
  the LDO not needed and should not supply
  3.3 ro the system
- DNP
- SMB:0x54
- Using +5VA as a source or optionaly source the tel via USB connector
sheet 3
- PORT A
- PORT B
- 0.02mA
- On board DB-9
  connector
- ESD protection in driver
- ESD protection in driver
- NOP
- SP330: no failsafe bias resistors are needed
- NOP
- PORT C
- PORT D
- ESD protection in driver
- ESD protection in driver
- NOP
- NOP
sheet 4
- TERMINATION PORT A
- I2C GPIO EXTENDER
- CONFIG SWITCHES PORTS A <-> D
- RS-232/RS-485 Switches
- Output modes and termination can be controlled via
  i2c and connected PC software.
- Port A
- I2C Address: 0x27
- SW ON -> RS-232
  SW OFF -> RS-485
- NOP
- NOP
- NOP
- Port B
- <- EPAD was added
- SW ON -> RS-232
  SW OFF -> RS-485
- XRA1201P: Internal 100K PU are enabled by default
- TERMINATION PORT B
- NOTE:
  Port control possible only if the switches are in OFF state
- Port C
- TERMINATION SELECT
- TERMINATION PORT C
- SW ON -> RS-232
  SW OFF -> RS-485
- DNP
- Port D
- SW ON -> RS-232
  SW OFF -> RS-485
- DNP
- TERMINATION PORT D
- Stitching capacitors
- Note:
  The default state is RS-485 half-duplex, with termination disconnected,
  SW7 Is controlling Half / Full 485 state.
  SW1, SW2, SW3, SW4 - controlling each port for RS-232 or RS-485
  individually.
  SW5 - Controls Half-duplex termination of 120R (only one differential )
  SW6 - Controls FULL duplex termination of 120R (only one differential )
- Full/Half Duplex Switch
- For all RS-485 ports:
  SW ON -> Half duplex
  SW OFF -> Full Duplex
